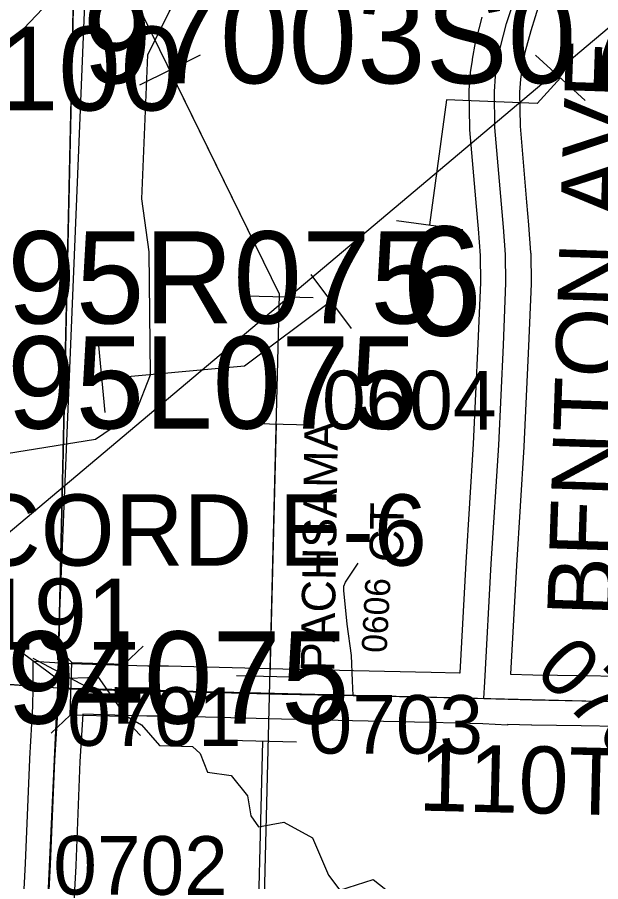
# Model space of a CAD drawing. Extents: x -157.2 to -99.3, y 12.2 to 46.2.
# Drawn here: x -144.502 to -143.805, y 39.918 to 40.949 of the extents above; entities that cross this region are included whole.
import ezdxf

# ---------------------------------------------------------------- set-up
doc = ezdxf.new("R2010")
doc.units = 0
for name, color, linetype in [('tdCoCityStreetMajor', 7, 'Continuous'), ('tdCoCorpBndry', 7, 'Continuous'), ('tdCoHydroRiver', 7, 'Continuous'), ('tdCoPipe', 7, 'Continuous'), ('tdCoRRCL', 7, 'Continuous'), ('tdCoSecRdNmbr', 7, 'Continuous'), ('tdCoSecRdTxt', 7, 'Continuous'), ('tdCoSecRteBand', 7, 'Continuous'), ('tdCoSecRteCL', 7, 'Continuous'), ('tdCoSectLine', 7, 'Continuous'), ('tdCoSectNmbr', 7, 'Continuous'), ('tdCoStrucPriMaintName', 7, 'Continuous'), ('tdCoStrucSec', 7, 'Continuous'), ('tdCoStrucSecCoName', 7, 'Continuous'), ('tdCoStrucSecFHWANum', 7, 'Continuous'), ('tdCoSurfAsphalt', 7, 'Continuous'), ('tdCoSurfConcUnbanded', 7, 'Continuous'), ('tdCoSurfGravel', 7, 'Continuous'), ('tdCoTwpBndry', 7, 'Continuous'), ('tdStHwyPriRefPost1', 7, 'Continuous'), ('tdStHwyPriRefPost5', 7, 'Continuous')]:
    doc.layers.add(name, color=color, linetype=linetype)

msp = doc.modelspace()

# ---------------------------------------------------------------- linework, layer by layer
at = {"layer": 'tdCoCityStreetMajor'}
msp.add_lwpolyline([(-144.6563, 40.1643), (-144.5228, 40.1538), (-144.4527, 40.1488)], dxfattribs=at)
at = {"layer": 'tdCoCorpBndry'}
msp.add_lwpolyline([(-144.5355, 38.1566), (-144.4989, 39.1588), (-144.4828, 39.5029), (-144.4746, 39.5028), (-144.4738, 39.6047), (-144.474, 39.6496), (-144.4741, 39.6804), (-144.4704, 39.7825), (-144.4679, 39.8227), (-144.4618, 39.9381), (-144.4568, 40.0626), (-144.4529, 40.1258), (-144.4527, 40.1488), (-144.4325, 41.0478), (-144.2491, 41.2426), (-144.3711, 41.2483), (-144.3636, 41.2415), (-144.3943, 41.2028), (-144.4298, 41.1658), (-144.4435, 41.1516), (-145.4178, 41.197), (-146.4155, 41.2271), (-147.4038, 41.2616)], dxfattribs=at)
at = {"layer": 'tdCoHydroRiver'}
for points in [[(-144.6141, 40.2379), (-144.5669, 40.3279), (-144.558, 40.3591), (-144.5294, 40.4102), (-144.5146, 40.4287), (-144.4083, 40.4457), (-144.3598, 40.4788), (-144.3426, 40.5224), (-144.3441, 40.6692), (-144.353, 40.7326), (-144.3457, 40.9044), (-144.3204, 40.9556), (-144.302, 40.9865)], [(-144.6141, 40.2379), (-144.6015, 40.2375), (-144.5805, 40.251), (-144.5584, 40.2518), (-144.528, 40.2146), (-144.4541, 40.1601), (-144.4051, 40.1616), (-144.3734, 40.1164), (-144.3533, 40.1047), (-144.332, 40.0803), (-144.2926, 40.079), (-144.2834, 40.0708), (-144.2747, 40.0485), (-144.2464, 40.0444), (-144.2267, 40.0201), (-144.2227, 39.9963), (-144.2137, 39.9833), (-144.1835, 39.9887), (-144.1494, 39.9702), (-144.1303, 39.9254), (-144.1167, 39.9076), (-144.0768, 39.9205), (-144.0522, 39.9007)]]:
    msp.add_lwpolyline(points, dxfattribs=at)
at = {"layer": 'tdCoPipe'}
for p, q in [((-144.2835, 40.9037), (-144.3558, 40.8682)), ((-143.8829, 40.9037), (-143.8236, 40.8498)), ((-143.8829, 40.9037), (-143.8236, 40.8498)), ((-144.0491, 40.7067), (-143.9697, 40.6958)), ((-144.0491, 40.7067), (-143.9697, 40.6958)), ((-144.1513, 40.6421), (-144.1032, 40.5779)), ((-144.1513, 40.6421), (-144.1032, 40.5779)), ((-144.1484, 40.6144), (-144.2288, 40.6164)), ((-144.4045, 40.5573), (-144.3973, 40.4775)), ((-144.4045, 40.5573), (-144.3973, 40.4775)), ((-144.1522, 40.4624), (-144.2327, 40.4644)), ((-144.1596, 40.1615), (-144.24, 40.1635)), ((-144.1684, 40.0841), (-144.249, 40.0861))]:
    msp.add_line(p, q, dxfattribs=at)
for points in [[(-144.5162, 38.9524), (-144.2247, 39.1641), (-144.1886, 40.6186), (-144.7421, 41.7477)], [(-143.342, 41.3185), (-144.5228, 40.3246)], [(-144.1887, 40.6154), (-144.1886, 40.6186), (-144.3196, 40.886)], [(-143.8533, 40.8767), (-143.8809, 40.8463), (-143.9891, 40.8505), (-144.0094, 40.7013)], [(-143.8533, 40.8767), (-143.8809, 40.8463), (-143.9891, 40.8505), (-144.0094, 40.7013)], [(-144.1272, 40.61), (-144.2304, 40.5327), (-144.4009, 40.5174)], [(-144.1272, 40.61), (-144.2304, 40.5327), (-144.4009, 40.5174)], [(-144.1999, 40.1625), (-144.1924, 40.4634)], [(-144.2162, 39.7842), (-144.2087, 40.0851)]]:
    msp.add_lwpolyline(points, dxfattribs=at)
at = {"layer": 'tdCoRRCL'}
msp.add_lwpolyline([(-143.9107, 41.5536), (-144.0814, 41.3683), (-144.2549, 41.1881), (-144.4266, 41.0069), (-144.5991, 40.8251), (-144.7709, 40.6451), (-144.9439, 40.4642), (-145.1435, 40.313)], dxfattribs=at)
at = {"layer": 'tdCoSecRteBand'}
for points in [[(-143.8782, 40.9661), (-143.8888, 40.933), (-143.8957, 40.907), (-143.8991, 40.8887), (-143.9011, 40.8754), (-143.9021, 40.8598), (-143.9014, 40.819), (-143.8936, 40.7285), (-143.8936, 40.7285), (-143.8936, 40.7284), (-143.8914, 40.7013), (-143.8914, 40.7012), (-143.8914, 40.7011), (-143.8889, 40.6683), (-143.8888, 40.6674), (-143.8888, 40.6665), (-143.8883, 40.6327), (-143.8883, 40.6319), (-143.8884, 40.631), (-143.8913, 40.5568), (-143.8913, 40.5567), (-143.8913, 40.5566), (-143.897, 40.437), (-143.897, 40.4368), (-143.897, 40.4365), (-143.9059, 40.2951), (-143.9129, 40.1653), (-143.8864, 40.1646), (-143.8274, 40.1636), (-143.7389, 40.1621)], [(-144.4979, 39.8244), (-144.4917, 39.9395), (-144.4868, 40.0638), (-144.4868, 40.0642), (-144.4868, 40.0645), (-144.4829, 40.1268), (-144.4827, 40.149), (-144.4825, 40.181), (-144.4506, 40.1787), (-144.4382, 40.1779), (-144.3456, 40.1752), (-144.3221, 40.1752), (-144.3217, 40.1752), (-144.3213, 40.1752), (-144.1848, 40.1715), (-144.1002, 40.1697), (-144.0075, 40.1678), (-144.0075, 40.1678), (-144.0074, 40.1678), (-143.9739, 40.1669), (-143.973, 40.1669), (-143.9658, 40.2985), (-143.9658, 40.2986), (-143.9658, 40.2987), (-143.9569, 40.4401), (-143.9513, 40.5593), (-143.9483, 40.6326), (-143.9488, 40.6647), (-143.9512, 40.6965), (-143.9534, 40.7234), (-143.9613, 40.8149), (-143.9614, 40.8159), (-143.9614, 40.8169), (-143.9621, 40.8601), (-143.9622, 40.8614), (-143.9621, 40.8626), (-143.9608, 40.8806), (-143.9608, 40.8818), (-143.9606, 40.883), (-143.9584, 40.898), (-143.9583, 40.8986), (-143.9582, 40.8991), (-143.9545, 40.9191), (-143.9543, 40.9202), (-143.954, 40.9213), (-143.9466, 40.9492)], [(-143.7401, 40.1021), (-143.8284, 40.1036), (-143.8876, 40.1046), (-143.8877, 40.1046), (-143.8879, 40.1046), (-143.9166, 40.1053), (-143.9166, 40.1043), (-143.9461, 40.1061), (-144.0089, 40.1078), (-144.1015, 40.1097), (-144.1861, 40.1115), (-144.1862, 40.1115), (-144.1863, 40.1115), (-144.3225, 40.1152), (-144.346, 40.1152), (-144.3464, 40.1152), (-144.3469, 40.1152), (-144.4233, 40.1174), (-144.4269, 40.0611), (-144.4318, 39.9369), (-144.4318, 39.9367), (-144.4318, 39.9365), (-144.438, 39.8211)]]:
    msp.add_lwpolyline(points, dxfattribs=at)
at = {"layer": 'tdCoSecRteCL'}
for points in [[(-143.9447, 40.1361), (-143.9435, 40.1561), (-143.9358, 40.2969), (-143.927, 40.4384), (-143.9213, 40.558), (-143.9183, 40.6322), (-143.9188, 40.666), (-143.9213, 40.6988), (-143.9235, 40.7259), (-143.9314, 40.8174), (-143.9321, 40.8606), (-143.9309, 40.8786), (-143.9287, 40.8936), (-143.925, 40.9136), (-143.9176, 40.9415), (-143.9065, 40.976)], [(-144.1008, 40.1397), (-144.1013, 40.1573), (-144.1026, 40.1876), (-144.1077, 40.2251), (-144.1117, 40.2653), (-144.1117, 40.2702), (-144.1097, 40.2749), (-144.0947, 40.2976)], [(-144.4679, 39.8227), (-144.4618, 39.9381), (-144.4568, 40.0626), (-144.4529, 40.1258), (-144.4527, 40.1488), (-144.4397, 40.1479), (-144.346, 40.1452), (-144.3221, 40.1452), (-144.1855, 40.1415), (-144.1008, 40.1397)], [(-144.1008, 40.1397), (-144.0082, 40.1378), (-143.9447, 40.1361)], [(-143.9447, 40.1361), (-143.8871, 40.1346), (-143.8279, 40.1336), (-143.7394, 40.1321), (-143.685, 40.1302)]]:
    msp.add_lwpolyline(points, dxfattribs=at)
at = {"layer": 'tdCoSectLine'}
for points in [[(-144.4531, 40.1488), (-144.4306, 41.151)], [(-145.4617, 40.2263), (-144.4531, 40.1488)], [(-144.4993, 39.1588), (-144.4531, 40.1488)], [(-144.4531, 40.1488), (-143.4354, 40.1241)]]:
    msp.add_lwpolyline(points, dxfattribs=at)
at = {"layer": 'tdCoStrucSec'}
for p, q in [((-144.4366, 40.1791), (-144.4581, 40.2019)), ((-144.374, 40.1773), (-144.3513, 40.1988)), ((-144.4384, 40.1165), (-144.4612, 40.095)), ((-144.3759, 40.1147), (-144.3544, 40.092))]:
    msp.add_line(p, q, dxfattribs=at)
msp.add_lwpolyline([(-144.4366, 40.1791), (-144.374, 40.1773), (-144.3759, 40.1147), (-144.4384, 40.1165)], close=True, dxfattribs=at)
at = {"layer": 'tdCoStrucSecFHWANum'}
msp.add_line((-144.4831, 40.1844), (-144.4134, 40.1473), dxfattribs=at)
at = {"layer": 'tdCoSurfAsphalt'}
msp.add_lwpolyline([(-144.4527, 40.1488), (-144.4397, 40.1479), (-144.346, 40.1452), (-144.3221, 40.1452), (-144.1855, 40.1415), (-144.1008, 40.1397), (-144.0082, 40.1378), (-143.9447, 40.1361), (-143.8871, 40.1346), (-143.8279, 40.1336), (-143.7394, 40.1321), (-143.685, 40.1302), (-143.6617, 40.1294), (-143.5707, 40.1284), (-143.4535, 40.1245), (-143.3527, 40.1222), (-143.2772, 40.1227), (-143.1638, 40.121), (-143.0569, 40.1183)], dxfattribs=at)
at = {"layer": 'tdCoSurfConcUnbanded'}
msp.add_lwpolyline([(-144.1008, 40.1397), (-144.1013, 40.1573), (-144.1026, 40.1876), (-144.1077, 40.2251), (-144.1117, 40.2653), (-144.1117, 40.2702), (-144.1097, 40.2749), (-144.0947, 40.2976)], dxfattribs=at)
at = {"layer": 'tdCoSurfGravel'}
for points in [[(-143.9447, 40.1361), (-143.9435, 40.1561), (-143.9358, 40.2969), (-143.927, 40.4384), (-143.9213, 40.558), (-143.9183, 40.6322), (-143.9188, 40.666), (-143.9213, 40.6988), (-143.9235, 40.7259), (-143.9314, 40.8174), (-143.9321, 40.8606), (-143.9309, 40.8786), (-143.9287, 40.8936), (-143.925, 40.9136), (-143.9176, 40.9415), (-143.9065, 40.976)], [(-144.474, 39.6496), (-144.4741, 39.6804), (-144.4704, 39.7825), (-144.4679, 39.8227), (-144.4618, 39.9381), (-144.4568, 40.0626), (-144.4529, 40.1258), (-144.4527, 40.1488)]]:
    msp.add_lwpolyline(points, dxfattribs=at)
at = {"layer": 'tdCoTwpBndry'}
msp.add_lwpolyline([(-144.4531, 40.1825), (-144.4151, 41.1098)], dxfattribs=at)

# ---------------------------------------------------------------- texts
at = {"layer": 'tdCoSecRdNmbr'}
for s, height, rotation, p in [('0604', 0.07, 359.8899, (-144.1379, 40.4575)), ('0606', 0.03, 86.8917, (-144.0608, 40.1901)), ('0705', 0.07, 315, (-143.8863, 40.167)), ('0701', 0.07, 359.8898, (-144.4422, 40.0799)), ('0703', 0.07, 359.8898, (-144.154, 40.0706)), ('0702', 0.07, 359.8897, (-144.4587, 39.9023))]:
    msp.add_text(s, height=height, rotation=rotation, dxfattribs=at).set_placement(p)
at = {"layer": 'tdCoSecRdTxt'}
for s, height, rotation, p in [('BENTON AVE', 0.08, 88.1011, (-143.7892, 40.2328)), ('PACHSAMA ', 0.04, 89.1337, (-144.1233, 40.1673)), (' CT', 0.04, 89.1337, (-144.0415, 40.2838)), ('110TH ST', 0.08, 358.6258, (-144.0231, 40.0026))]:
    msp.add_text(s, height=height, rotation=rotation, dxfattribs=at).set_placement(p)
at = {"layer": 'tdCoSectNmbr'}
msp.add_text('6', height=0.13, rotation=359.89, dxfattribs=at).set_placement((-144.0431, 40.5694))
at = {"layer": 'tdCoStrucPriMaintName'}
for s, p in [('97003S075', (-144.4233, 40.8703)), ('97995R075', (-144.759, 40.5837)), ('97995L075', (-144.7593, 40.4583)), ('97994075', (-144.7595, 40.1063))]:
    msp.add_text(s, height=0.11, dxfattribs=at).set_placement(p)
at = {"layer": 'tdCoStrucSecCoName'}
msp.add_text('CONCORD E-6', height=0.085, dxfattribs=at).set_placement((-144.8084, 40.2948))
at = {"layer": 'tdCoStrucSecFHWANum'}
msp.add_text('355191', height=0.085, dxfattribs=at).set_placement((-144.7347, 40.1944))
at = {"layer": 'tdStHwyPriRefPost1'}
msp.add_text('‒‒100', height=0.1, dxfattribs=at).set_placement((-144.6757, 40.8379))
at = {"layer": 'tdStHwyPriRefPost5'}
msp.add_text('‒‒100', height=0.1, dxfattribs=at).set_placement((-144.6757, 40.8379))

doc.saveas('drawing.dxf')
